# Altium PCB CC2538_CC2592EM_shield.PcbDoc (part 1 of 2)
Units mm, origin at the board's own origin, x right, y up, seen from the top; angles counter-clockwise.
Board outline 41.63 x 56.78 mm, 4 copper layers (TOP, L2, L3, BOTTOM), stack 1.596 mm thick; 77 components, 70 nets, 284 pads, 581 vias.
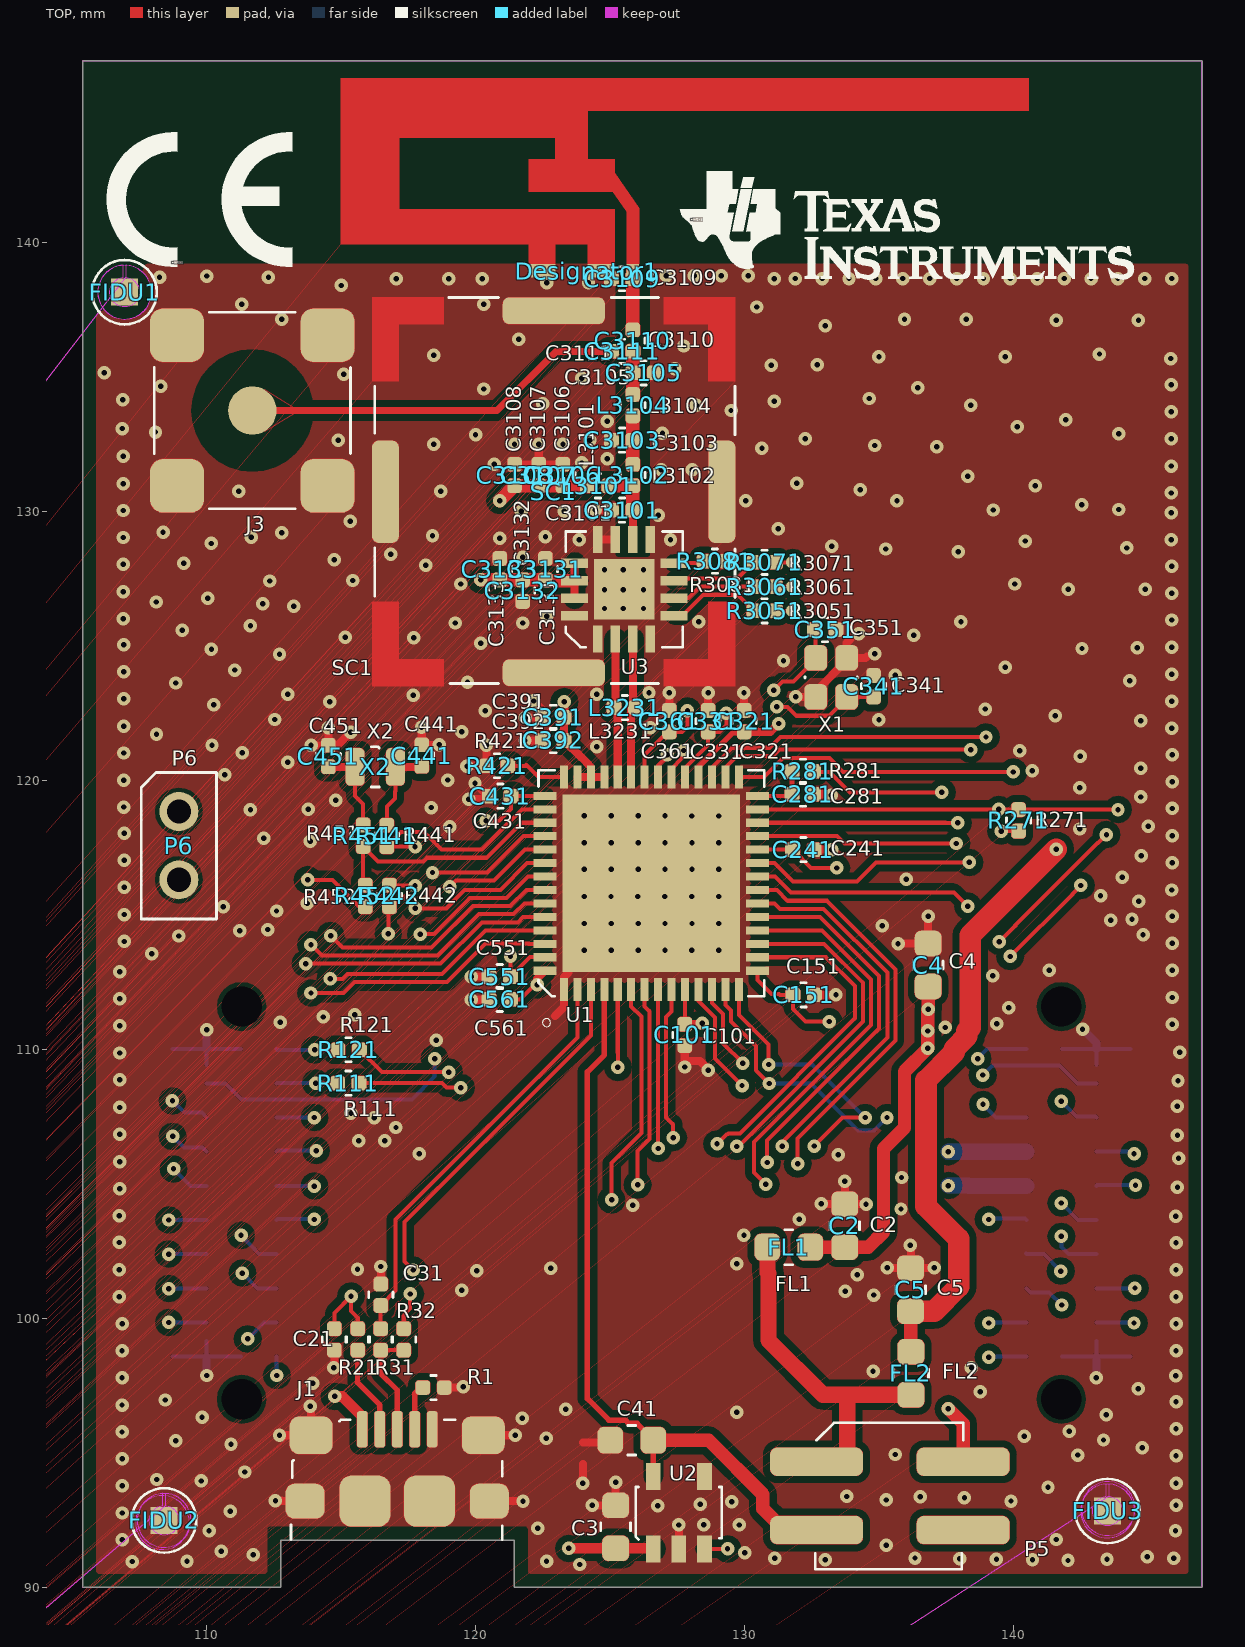
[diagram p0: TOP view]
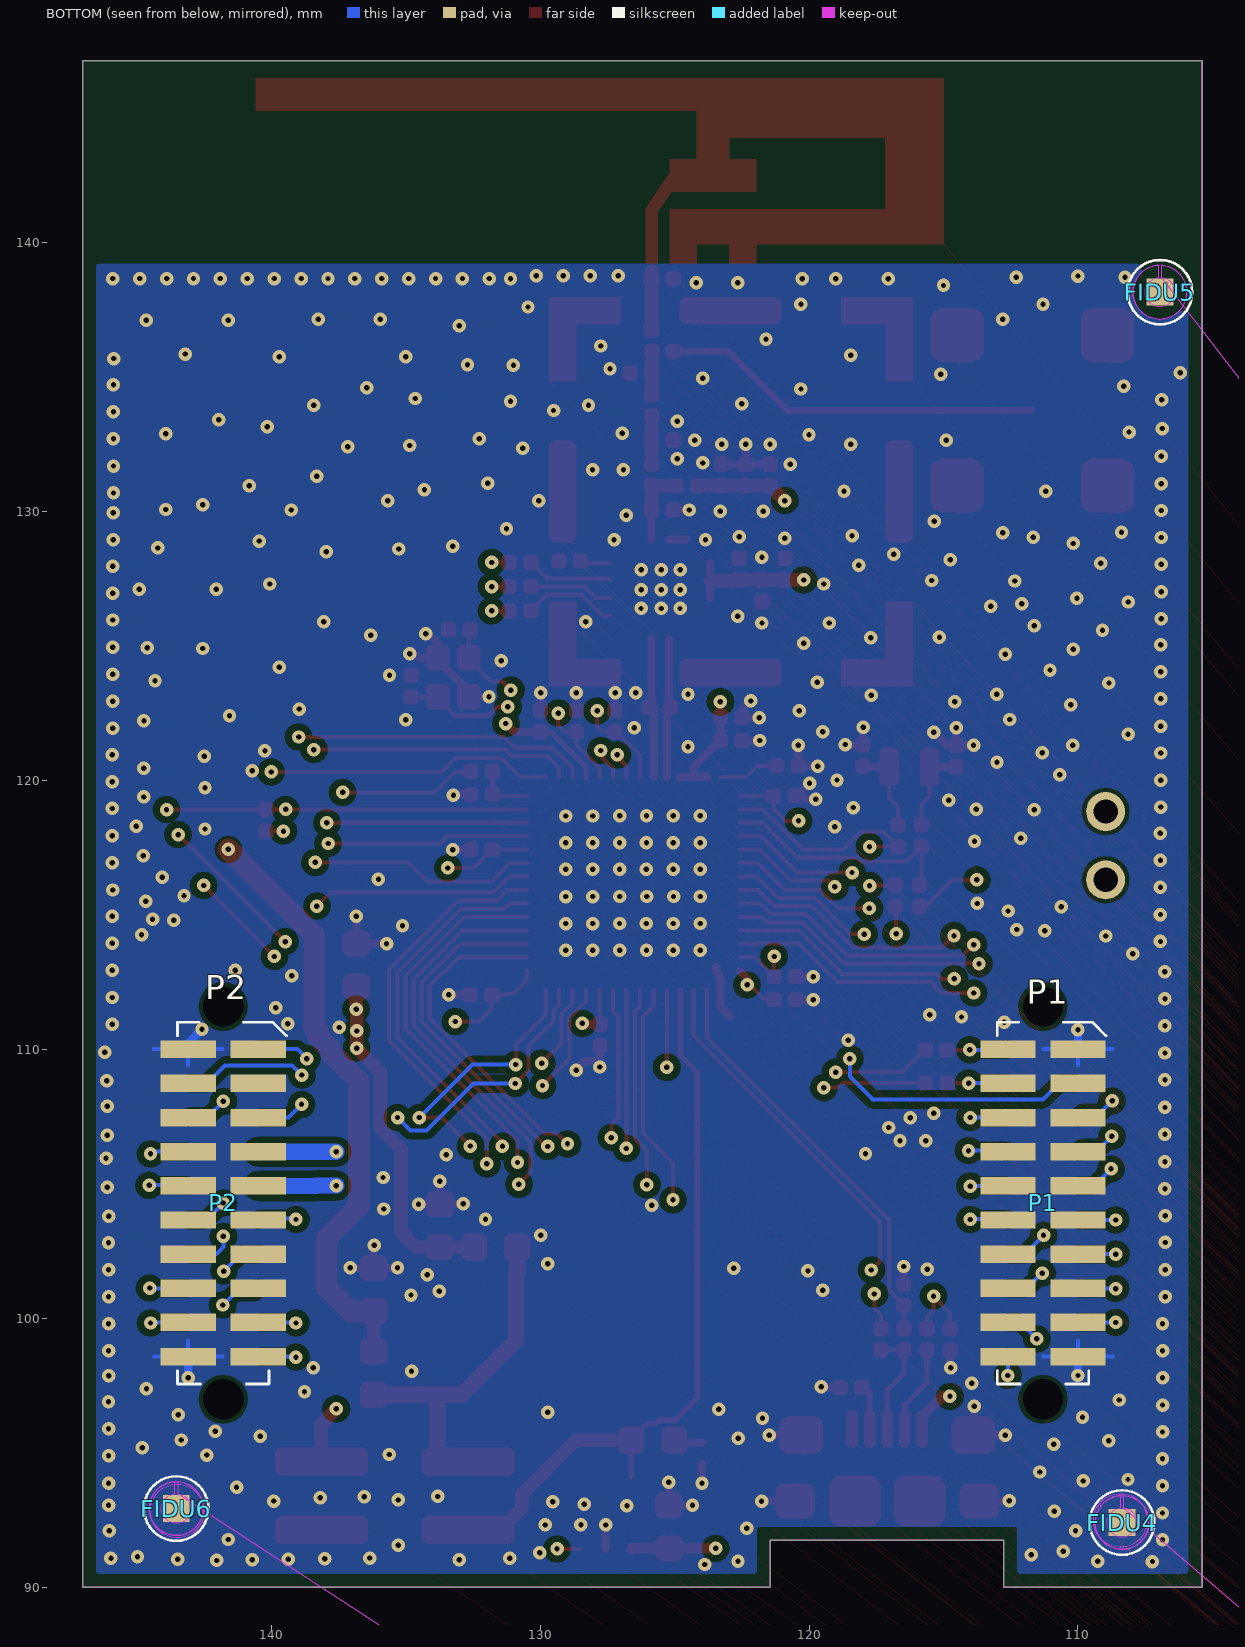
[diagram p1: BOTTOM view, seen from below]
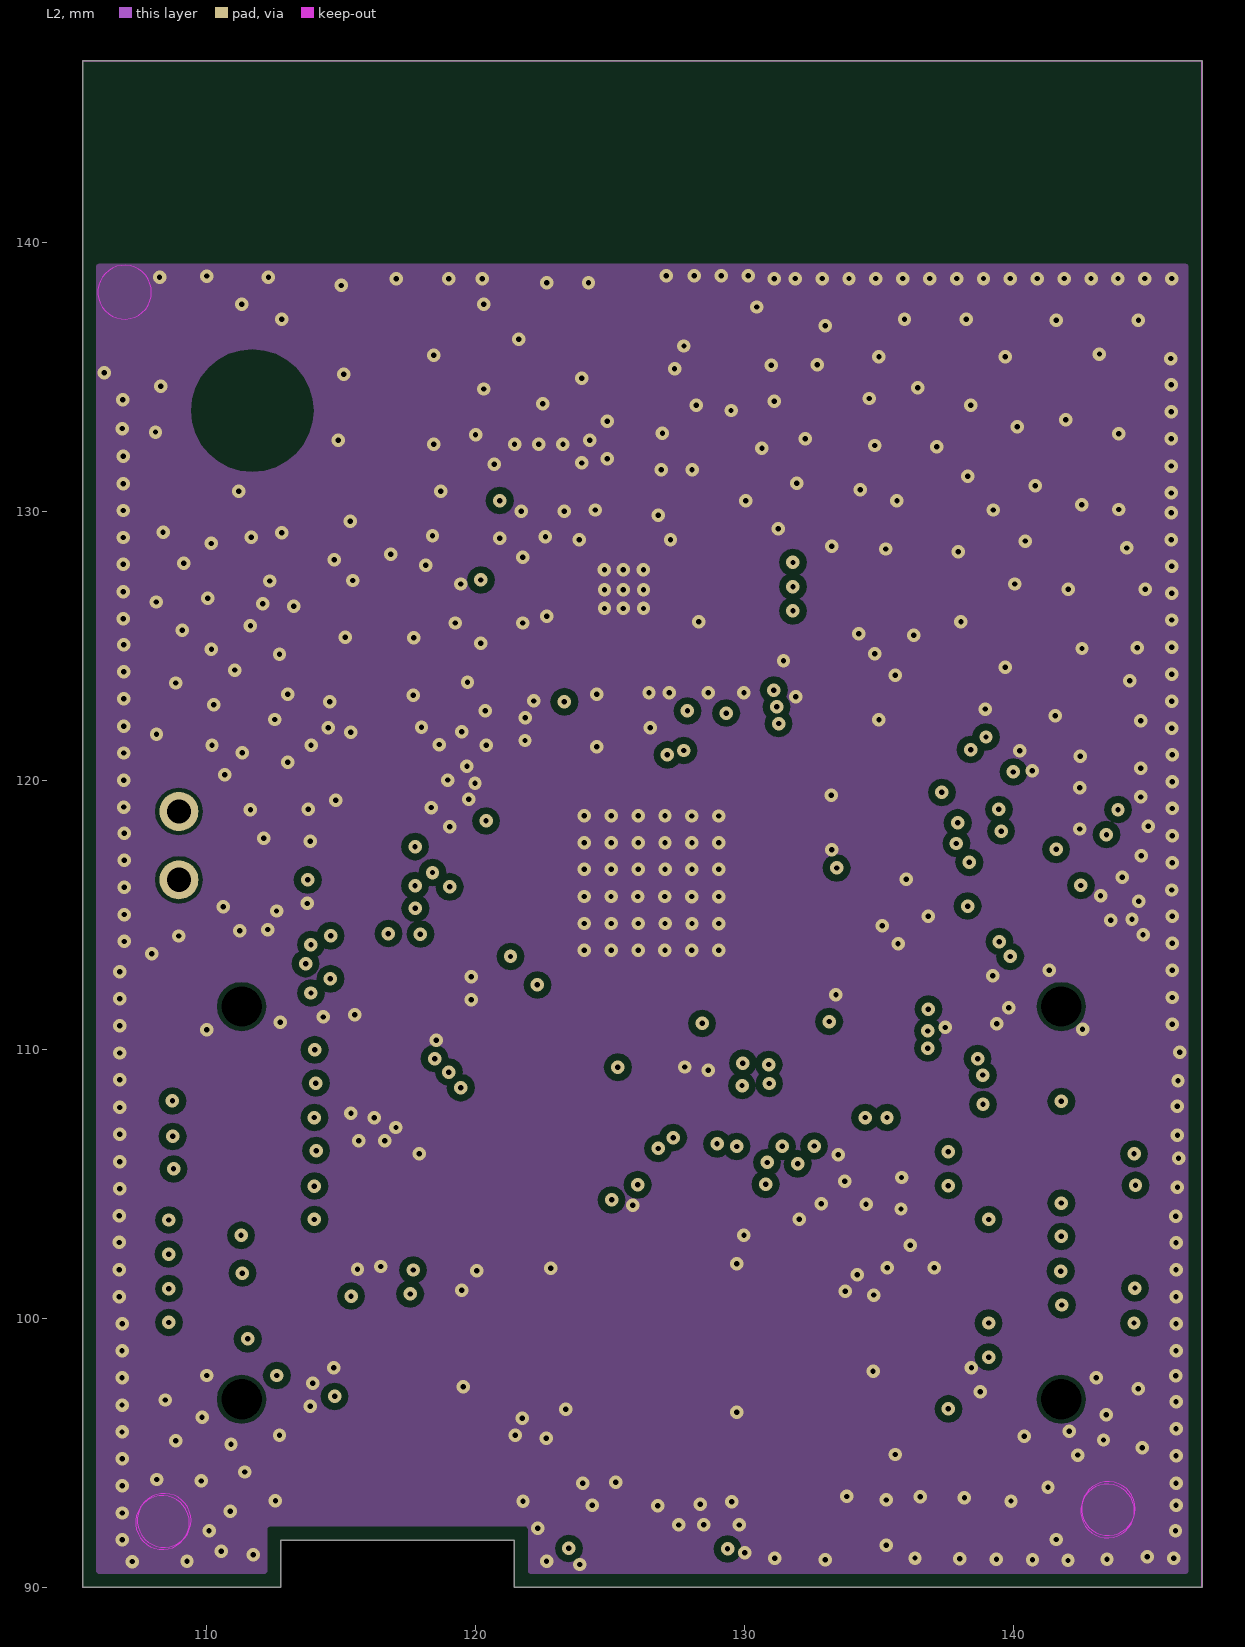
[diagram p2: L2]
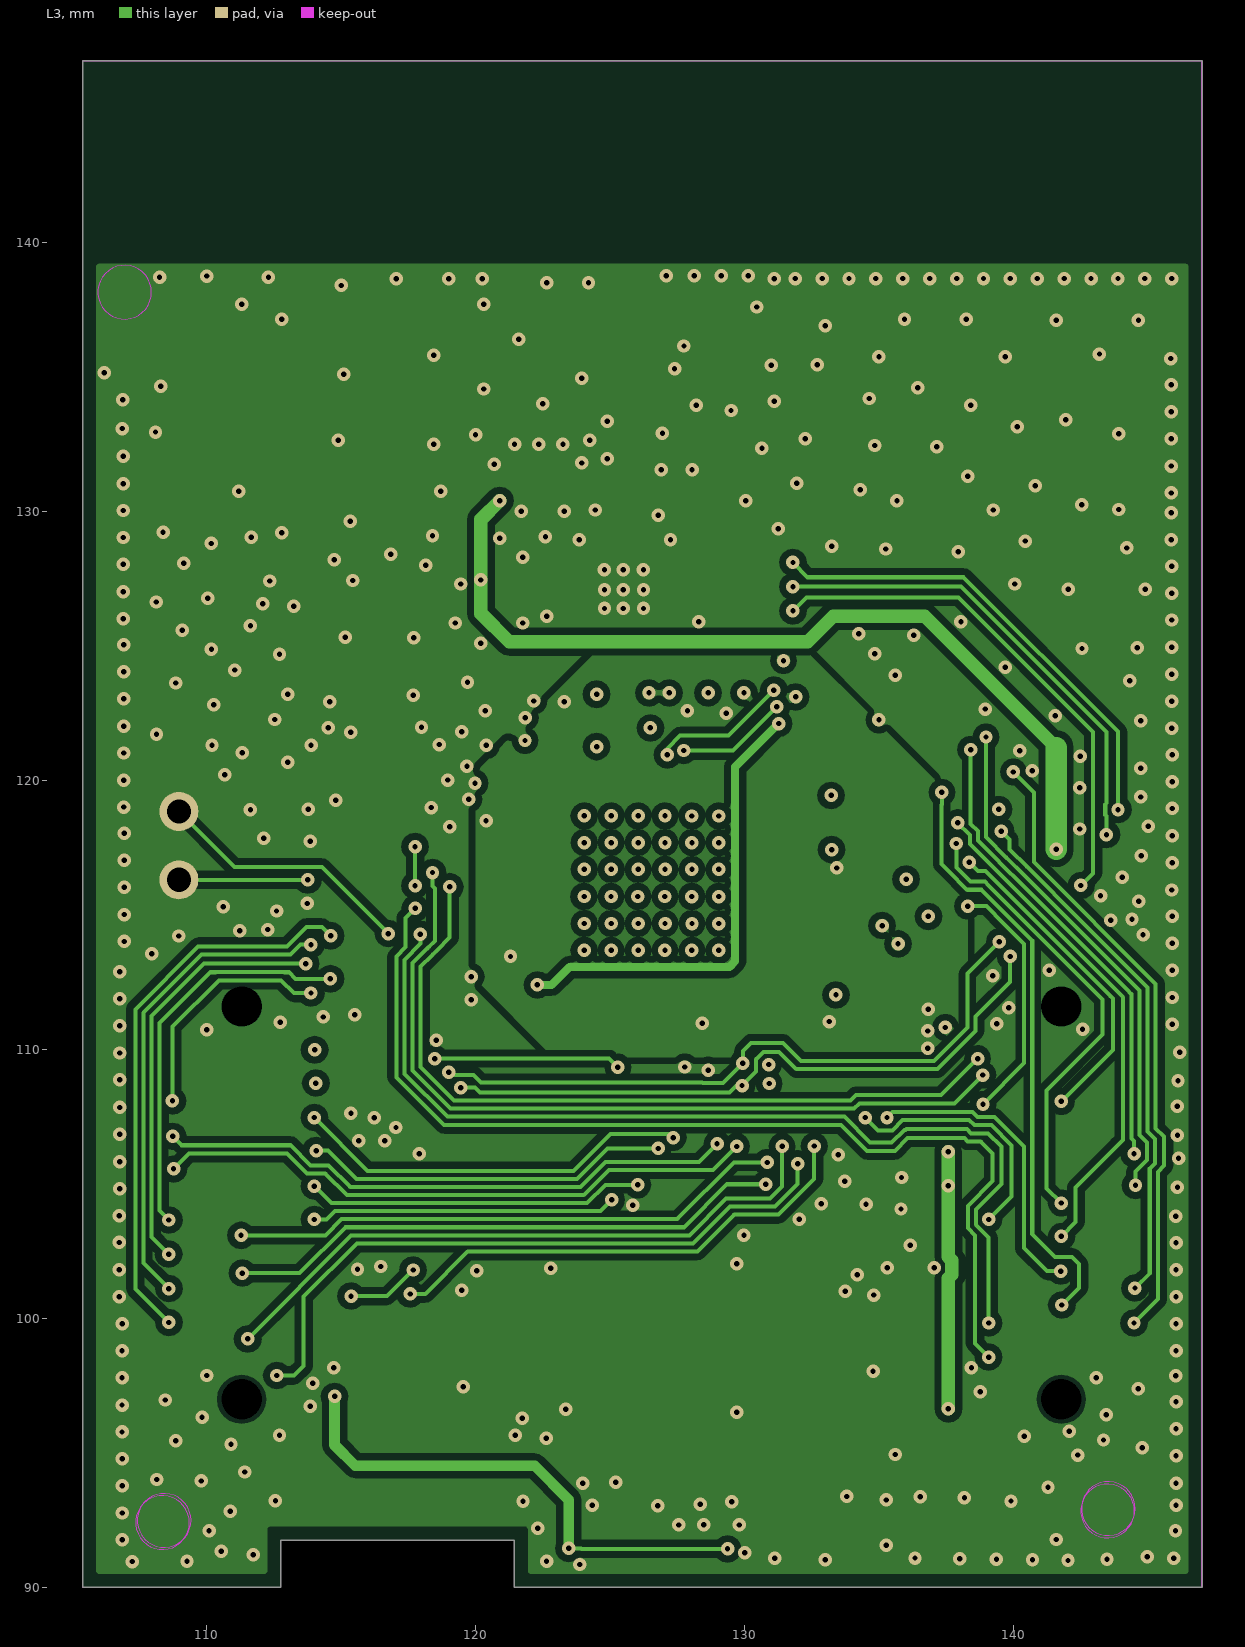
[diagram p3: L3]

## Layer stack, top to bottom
Top Solder: solder mask 0.0102, Solder Resist, Dk 3.5
TOP: signal copper 0.035
Dielectric 1: core 0.175, FR-4, Dk 4.5
L2: signal copper 0.018
Dielectric2: core 1.14, FR-4, Dk 4.5
L3: signal copper 0.018
Dielectric3: core 0.175, FR-4, Dk 4.5
BOTTOM: signal copper 0.035
Bottom Solder: solder mask 0.0102, Solder Resist, Dk 3.5

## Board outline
105.387,90 105.4,89.987 112.75,89.987 112.763,90 112.763,91.737 121.437,91.737 121.437,90 121.45,89.987 147,89.987 147.013,90 147.013,146.75 147,146.763 105.4,146.763 105.387,146.75

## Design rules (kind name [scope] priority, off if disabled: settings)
Clearance [All] p1: gap=0.254
PlaneConnect [All] p1: planeconnectstyle=Direct reliefexpansion=0.508 reliefentries=4 reliefconductorwidth=0.254 reliefairgap=0.254
PolygonConnect [All] p1: connectstyle=Direct reliefconductorwidth=0.254 reliefentries=4 polygonreliefangle="90 Angle" airgapwidth=0.254
RoomDefinition CompsKeepin0 [All vs False] p1: confinementstyle=ConfineIn formatcopy=TRUE lockcomponents=FALSE outline 105.9,152.12 146.5,152.12 146.5,90.5 122.1,90.5 122.1,90.09 112.13,90.09 112.13,90.5 105.9,90.5 105.9,152.12
RoutingVias [All] p1: holewidth=0.711 width=1.27 viastyle="Through Hole" minholewidth=0.711 minwidth=1.27 maxholewidth=0.711 maxwidth=1.27
SolderMaskExpansion [All] p1: expansion=0.102
Width [All] p1: maxlimit=0.254 minlimit=0.254 preferedwidth=0.254 impedancedriven=TRUE minimp=35.860000 maximp=35.860000 favimp=35.860000
29 further rules are at their usual default settings.

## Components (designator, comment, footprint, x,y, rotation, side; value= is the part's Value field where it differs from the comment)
C2 "CAPACITOR_CAPC1608X90N_2.2UF" CAPC1608X90N 133.73,103.44 r90 top
C3 "CAPACITOR_CAPC1608X90N_1UF" CAPC1608X90N 125.21,92.24 r90 top
C4 "CAPACITOR_CAPC1608X90N_DNM_CAPC" CAPC1608X90N 136.83,113.13 r90 top
C5 "CAPACITOR_CAPC1608X90N_2.2UF" CAPC1608X90N 136.18,101.06 r90 top
C21 "CAPACITOR_CAPC1005X60L_47PF_CAP" CAPC1005X60L 114.75,99.21 r270 top
C31 "CAPACITOR_CAPC1005X60L_47PF_CAP" CAPC1005X60L 116.48,100.87 r90 top
C41 "CAPACITOR_CAPC1608X90N_1UF" CAPC1608X90N 125.81,95.46 r180 top
C101 "CAPACITOR_CAPC1005X60L_100NF_CA" CAPC1005X60L 127.78,110.53 r270 top
C151 "CAPACITOR_CAPC1005X60L_100NF_CA" CAPC1005X60L 132.2,112.02 r0 top
C241 "CAPACITOR_CAPC1005X60L_100NF_CA" CAPC1005X60L 132.19,117.42 r0 top
C281 "CAPACITOR_CAPC1005X60L_1NF_CAPC" CAPC1005X60L 132.17,119.48 r0 top
C321 "CAPACITOR_CAPC1005X60L_1UF_CAPC" CAPC1005X60L 129.99,122.2 r90 top
C331 "CAPACITOR_CAPC1005X60L_100NF_CA" CAPC1005X60L 128.65,122.2 r90 top
C341 "CAPACITOR_CAPC1005X60L_12PF_CAP" CAPC1005X60L 134.8,123.5 r90 top
C351 "CAPACITOR_CAPC1005X60L_12PF_CAP" CAPC1005X60L 133,125.6 r0 top
C361 "CAPACITOR_CAPC1005X60L_100NF_CA" CAPC1005X60L 127.21,122.2 r90 top
C391 "CAPACITOR_CAPC1005X60L_100NF_CA" CAPC1005X60L 122.89,122.34 r180 top
C392 "CAPACITOR_CAPC1005X60L_220PF_CA" CAPC1005X60L 122.89,121.48 r180 top
C431 "CAPACITOR_CAPC1005X60L_100NF_CA" CAPC1005X60L 120.92,119.41 r180 top
C441 "CAPACITOR_CAPC1005X60L_22PF_CAP" CAPC1005X60L 118,120.92 r90 top
C451 "CAPACITOR_CAPC1005X60L_22PF_CAP" CAPC1005X60L 114.53,120.9 r90 top
C551 "CAPACITOR_CAPC1005X60L_1UF_CAPC" CAPC1005X60L 120.9,112.7 r180 top
C561 "CAPACITOR_CAPC1005X60L_1UF_CAPC" CAPC1005X60L 120.9,111.85 r180 top
C3101 "CAPACITOR_CAPC1005X60L_3PF_CAPC" CAPC1005X60L 125.45,130.05 r180 top
C3103 "CAPACITOR_CAPC1005X60L_2.2PF_CA" CAPC1005X60L 125.45,132.65 r180 top
C3105 "CAPACITOR_CAPC1005X60L_0.2PF_CA" CAPC1005X60L 126.25,135.15 r0 top
C3106 "CAPACITOR_CAPC1005X60L_6.8PF_CA" CAPC1005X60L 123.25,131.35 r90 top
C3107 "CAPACITOR_CAPC1005X60L_1NF_CAPC" CAPC1005X60L 122.35,131.35 r90 top
C3108 "CAPACITOR_CAPC1005X60L_1UF_CAPC" CAPC1005X60L 121.45,131.35 r90 top
C3109 "CAPACITOR_CAPC1005X60L_DNM_CAPC" CAPC1005X60L 125.45,138.65 r180 top
C3110 "CAPACITOR_HOR_CAPC1005X60L_12PF" CAPC1005X60L 125.85,136.35 r90 top
C3111 "CAPACITOR_CAPC1005X60L_DNM_CAPC" CAPC1005X60L 125.45,135.95 r0 top
C3131 "CAPACITOR_CAPC1005X60L_12PF_CAP" CAPC1005X60L 122.6,127.85 r90 top
C3132 "CAPACITOR_CAPC1005X60L_1NF_CAPC" CAPC1005X60L 121.75,127.05 r270 top
C3133 "CAPACITOR_CAPC1005X60L_DNM_CAPC" CAPC1005X60L 120.9,127.85 r90 top
Designator1 "ANTENNA_DN007_ANTENNA_DN007_DN0" ANTENNA_DN007 127.78,142.955 r0 top
FIDU1 "FIDMARK_FID100X115_FIDU_1MM" FID100X115 106.95,138.15 r0 top
FIDU2 "FIDMARK_FID100X115_FIDU_1MM" FID100X115 108.42,92.48 r0 top
FIDU3 "FIDMARK_FID100X115_FIDU_1MM" FID100X115 143.5,92.83 r0 top
FIDU4 "FIDMARK_FID100X115_FIDU_1MM" FID100X115 108.36,92.4 r0 bottom
FIDU5 "FIDMARK_FID100X115_FIDU_1MM" FID100X115 106.95,138.15 r0 bottom
FIDU6 "FIDMARK_FID100X115_FIDU_1MM" FID100X115 143.53,92.92 r0 bottom
FL1 "FILTER_2PIN_FIL_BLM18HE152SN1DN" FIL_BLM18HE152SN1DN 131.65,102.64 r180 top
FL2 "FILTER_2PIN_FIL_BLM18HE152SN1_1" FIL_BLM18HE152SN1DN 136.19,97.95 r270 top
J1 "CONN_USB_MICRO_5+6_S_TYCO_19815" TYCO_19815681N 117.087,93.245 r270 top
J3 "CONN_COAX_1+4_HUSTSAN_SMA10V21T" HUSTSAN_SMA10V21TGGAN 111.7,133.75 r0 top
L3101 "INDUCTOR_INDC1005X60L_4.7NH_IND" INDC1005X60L 124.55,130.95 r0 top
L3102 "INDUCTOR_HOR_INDC1005X60L_1NH_I" INDC1005X60L 125.85,131.35 r90 top
L3104 "INDUCTOR_INDC1005X60L_1.8NH_IND" INDC1005X60L 125.85,133.95 r90 top
L3231 "INDUCTOR_INDC1005X60L_10NH_INDC" INDC1005X60L 125.55,122.7 r180 top
P1 "CONN_HEADER_2X10_P_S_SAMTEC_SFM" SAMTEC_SFM11002AN 111.27,104.285 r180 bottom
P2 "CONN_HEADER_2X10_P_S_SAMTEC_SFM" SAMTEC_SFM11002AN 141.75,104.285 r180 bottom
P5 "CONN_HEADER_2X2_P_S_GRADCONN_BB" GRADCONN_BB02HP041KB3060B00-4N 135.405,93.39 r270 top
P6 "CONN_HEADER_2_TYCO_826629-2B_82" TYCO_826629-2B 108.97,117.57 r270 top
R1 "RESISTOR_RESC1005X40L_DNM_RESC1" RESC1005X40L 118.44,97.42 r180 top
R21 "RESISTOR_RESC1005X40L_33_RESC10" RESC1005X40L 115.62,99.21 r270 top
R31 "RESISTOR_RESC1005X40L_33_RESC10" RESC1005X40L 116.47,99.21 r270 top
R32 "RESISTOR_RESC1005X40L_1.5K_RESC" RESC1005X40L 117.33,99.21 r90 top
R111 "RESISTOR_RESC1005X40L_DNM_RESC1" RESC1005X40L 115.27,108.74 r180 top
R121 "RESISTOR_RESC1005X40L_DNM_RESC1" RESC1005X40L 115.28,109.98 r180 top
R271 "RESISTOR_RESC1005X40L_DNM_RESC1" RESC1005X40L 140.19,118.51 r90 top
R281 "RESISTOR_RESC1005X40L_2.2K_RESC" RESC1005X40L 132.17,120.33 r180 top
R421 "RESISTOR_RESC1005X40L_56K_RESC1" RESC1005X40L 120.8,120.54 r0 top
R441 "RESISTOR_RESC1005X40L_0_RESC100" RESC1005X40L 116.7,117.93 r90 top
R442 "RESISTOR_RESC1005X40L_DNM_RESC1" RESC1005X40L 116.8,115.7 r90 top
R451 "RESISTOR_RESC1005X40L_0_RESC100" RESC1005X40L 115.82,117.94 r90 top
R452 "RESISTOR_RESC1005X40L_DNM_RESC1" RESC1005X40L 115.9,115.7 r90 top
R3051 "RESISTOR_RESC1005X40L_10K_RESC1" RESC1005X40L 130.75,126.3 r180 top
R3061 "RESISTOR_RESC1005X40L_10K_RESC1" RESC1005X40L 130.75,127.2 r180 top
R3071 "RESISTOR_RESC1005X40L_10K_RESC1" RESC1005X40L 130.75,128.1 r180 top
R3081 "RESISTOR_RESC1005X40L_4.7K_RESC" RESC1005X40L 128.9,128.15 r0 top
SC1 "SHIELD_COVER_BMIS-201_MECH_BMIS" MECH_BMIS201 122.905,130.73 r0 top
U1 "IC_RF_CC2538F512_QFN56_1_QFNFC5" QFNFC50P800X800X100-57AN 126.539,116.17 r0 top
U2 "IC_PM_TLV700233_SOT23-5_SOT95P2" SOT95P280X145-5N 127.56,92.77 r0 top
U3 "IC_RF_CC2592_QFN16_2_QFNFC65P40" QFNFC65P400X400X100-17AN 125.525,127.1 r0 top
X1 "XTAL_4_XTAL_FA128N_32MHZ" XTAL_FA128N 133.226,123.826 r90 top
X2 "XTAL_XTAL_FC12MN_32.768KHZ_XTAL" XTAL_FC12MN 116.27,120.5 r180 top

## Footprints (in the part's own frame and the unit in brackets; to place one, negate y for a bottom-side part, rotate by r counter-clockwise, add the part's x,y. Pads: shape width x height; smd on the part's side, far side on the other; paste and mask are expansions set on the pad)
ANTENNA_DN007 [mm] "ANTENNA_DN007"
  rect 0.46x0.5 smd: 1(-1.93,-4.005)
  rect 1x0.5 smd: 2(-3.11,-4.005) 3(-5.31,-4.005)
  TOP region: -12.79,-3.015 -12.79,3.155 12.79,3.155 12.79,1.945 -3.61,1.945 -3.61,0.145 -2.61,0.145 -2.61,-0.357 -1.7,-1.677 -1.7,-3.755 -2.16,-3.755 -2.16,-1.82 -2.681,-1.065 -5.81,-1.065 -5.81,0.145 -4.81,0.145 -4.81,0.945 -10.61,0.945 -10.61,-1.725 -2.61,-1.725 -2.61,-3.755 -3.61,-3.755 -3.61,-3.015 -4.81,-3.015 -4.81,-3.755 -5.81,-3.755 -5.81,-3.015 -12.79,-3.015 -127.78,-142.955
CAPC1005X60L [mm] "CAPC1005X60L"
  rrect50% 0.55x0.54 smd: 1(-0.4,0) 2(0.4,0)
  silkscreen extent -0.1,-0.45 0.1,0.45
CAPC1608X90N [mm] "CAPC1608X90N"
  rrect50% 0.954x1 smd: 1(-0.8,0) 2(0.8,0)
  silkscreen extent -0.15,-0.55 0.15,0.55
FID100X115 [mm] "FID100X115"
  rrect0% 1x1 smd: 1(0,0)
  TOP keep-out region: 0.05,0.55 0.05,0.55 0.098,0.543 0.144,0.532 0.19,0.518 0.235,0.499 0.277,0.477 0.317,0.451 0.355,0.421 0.391,0.389 0.423,0.353 0.452,0.315 0.478,0.274 0.5,0.231 0.518,0.187 0.532,0.141 0.542,0.094 0.548,0.046 0.55,-0.002 0.548,-0.05 0.541,-0.098 0.53,-0.144 0.516,-0.19 0.497,-0.235 0.475,-0.277 0.449,-0.317 0.419,-0.355 0.387,-0.391 0.351,-0.423 0.313,-0.452 0.272,-0.478 0.229,-0.5 0.185,-0.518 0.139,-0.532 0.092,-0.542 0.044,-0.548 0,-0.55 0,-0.55 -0.048,-0.548 -0.096,-0.541 -0.143,-0.531 -0.188,-0.516 -0.233,-0.498 -0.275,-0.476 -0.316,-0.45 -0.354,-0.42 -0.389,-0.388 -0.422,-0.352 -0.451,-0.314 -0.477,-0.274 -0.499,-0.231 -0.517,-0.187 -0.531,-0.141 -0.542,-0.094 -0.548,-0.046 -0.55,0.002 -0.548,0.05 -0.541,0.098 -0.531,0.145 -0.516,0.19 -0.498,0.235 -0.476,0.277 -0.45,0.318 -0.42,0.356 -0.388,0.391 -0.352,0.424 -0.314,0.453 -0.274,0.479 -0.231,0.501 -0.187,0.519 -0.141,0.533 -0.094,0.544 -0.05,0.55 -0.05,1 -0.05,1.001 -0.137,0.992 -0.223,0.977 -0.307,0.953 -0.389,0.923 -0.468,0.885 -0.543,0.841 -0.614,0.791 -0.681,0.734 -0.742,0.672 -0.798,0.604 -0.847,0.533 -0.89,0.457 -0.927,0.377 -0.956,0.295 -0.978,0.21 -0.992,0.124 -0.999,0.037 -0.999,-0.05 -0.99,-0.137 -0.975,-0.223 -0.951,-0.307 -0.921,-0.389 -0.883,-0.468 -0.839,-0.543 -0.789,-0.614 -0.732,-0.681 -0.67,-0.742 -0.602,-0.798 -0.531,-0.847 -0.455,-0.89 -0.375,-0.927 -0.293,-0.956 -0.208,-0.978 -0.122,-0.992 -0.035,-0.999 0,-1 0,-1 0.087,-0.996 0.174,-0.985 0.259,-0.966 0.342,-0.939 0.423,-0.906 0.5,-0.865 0.574,-0.818 0.643,-0.765 0.708,-0.706 0.766,-0.642 0.82,-0.572 0.866,-0.499 0.907,-0.421 0.94,-0.34 0.966,-0.257 0.985,-0.172 0.996,-0.085 1,0.002 0.996,0.089 0.985,0.176 0.966,0.261 0.939,0.344 0.906,0.425 0.865,0.502 0.818,0.576 0.765,0.645 0.706,0.71 0.642,0.768 0.572,0.822 0.499,0.868 0.421,0.909 0.34,0.942 0.257,0.968 0.172,0.987 0.085,0.998 0.05,1 0.05,0.55 -106.95,-138.15
  Multi-Layer keep-out circle w0.025: c0,0 r1
  silkscreen extent -1.2,-1.2 1.2,1.2
FIL_BLM18HE152SN1DN [mm] "FIL_BLM18HE152SN1DN"
  rrect50% 0.954x1 smd: 1(-0.8,0) 2(0.8,0)
  silkscreen extent -0.15,-0.65 0.15,0.65
GRADCONN_BB02HP041KB3060B00-4N [mm] "GRADCONN_BB02HP041KB3060B00-4N"
  rrect50% 1.05x3.45 smd: 1(-1.27,-2.725) 2(-1.27,2.725) 3(1.27,-2.725) 4(1.27,2.725)
  silkscreen extent -2.72,-2.78 2.73,2.73
HUSTSAN_SMA10V21TGGAN [mm] "HUSTSAN_SMA10V21TGGAN"
  round 1.801 smd: 1(0,0)
  rrect48% 2x2 smd: 2(-2.8,-2.8) 3(2.8,-2.8) 4(2.8,2.8) 5(-2.8,2.8)
  silkscreen extent -3.65,-3.65 3.65,3.65
INDC1005X60L [mm] "INDC1005X60L"
  rrect50% 0.55x0.54 smd: 1(-0.4,0) 2(0.4,0)
  silkscreen extent -0.1,-0.45 0.1,0.45
MECH_BMIS201 [mm] "MECH_BMIS201"
  oct 0.025x0.025 smd: 1(-6.255,-6.73) 3(6.255,-6.73) 5(6.255,6.73) 7(-6.255,6.73)
  rrect50% 3.8x1 smd: 2(0.005,-6.73) 6(0.005,6.73)
  rrect50% 1x3.8 smd: 4(6.255,0) 8(-6.255,0)
  silkscreen extent -6.65,-7.13 6.75,7.22
QFNFC50P800X800X100-57AN [mm] "QFNFC50P800X800X100-57AN"
  rrect0% 0.3x0.851 smd: 1(-3.25,-3.949) 2(-2.75,-3.949) 3(-2.249,-3.949) 4(-1.749,-3.949) 5(-1.251,-3.949) 6(-0.751,-3.949) 7(-0.25,-3.949) 8(0.25,-3.949) 9(0.75,-3.949) 10(1.251,-3.949) 11(1.751,-3.949) 12(2.249,-3.949) 13(2.75,-3.949) 14(3.25,-3.949) 29(3.25,3.95) 30(2.75,3.95) 31(2.249,3.95) 32(1.751,3.95) 33(1.251,3.95) 34(0.75,3.95) 35(0.25,3.95) 36(-0.25,3.95) 37(-0.751,3.95) 38(-1.251,3.95) 39(-1.749,3.95) 40(-2.249,3.95) 41(-2.75,3.95) 42(-3.25,3.95)
  rrect0% 0.851x0.3 smd: 15(3.951,-3.251) 16(3.951,-2.75) 17(3.951,-2.25) 18(3.951,-1.75) 19(3.951,-1.249) 20(3.951,-0.749) 21(3.951,-0.251) 22(3.951,0.249) 23(3.951,0.75) 24(3.951,1.25) 25(3.951,1.751) 26(3.951,2.251) 27(3.951,2.749) 28(3.951,3.249) 43(-3.951,3.249) 44(-3.951,2.749) 45(-3.951,2.251) 46(-3.951,1.751) 47(-3.951,1.25) 48(-3.951,0.75) 49(-3.951,0.249) 50(-3.951,-0.251) 51(-3.951,-0.749) 52(-3.951,-1.249) 53(-3.951,-1.75) 54(-3.951,-2.25) 55(-3.951,-2.75) 56(-3.951,-3.251)
  rect 6.599x6.599 smd: 57(0.001,0)
  silkscreen extent -4.2,-5.33 4.2,4.2
QFNFC65P400X400X100-17AN [mm] "QFNFC65P400X400X100-17AN"
  rrect0% 0.35x1 smd: 1(-0.975,-1.85) 2(-0.325,-1.85) 3(0.325,-1.85) 4(0.975,-1.85) 9(0.975,1.85) 10(0.325,1.85) 11(-0.325,1.85) 12(-0.975,1.85)
  rrect0% 1x0.35 smd: 5(1.85,-0.975) 6(1.85,-0.325) 7(1.85,0.325) 8(1.85,0.975) 13(-1.85,0.975) 14(-1.85,0.325) 15(-1.85,-0.325) 16(-1.85,-0.975)
  rect 2.25x2.25 smd: 17(0,0)
  silkscreen extent -2.17,-2.15 2.18,2.15
RESC1005X40L [mm] "RESC1005X40L"
  rrect50% 0.55x0.54 smd: 1(-0.4,0) 2(0.4,0)
  silkscreen extent -0.1,-0.45 0.1,0.45
SAMTEC_SFM11002AN [mm] "SAMTEC_SFM11002AN"
  rrect0% 2.05x0.65 smd: 1(1.27,5.715) 2(-1.334,5.715) 3(1.27,4.445) 4(-1.334,4.445) 5(1.27,3.175) 6(-1.334,3.175) 7(1.27,1.905) 8(-1.334,1.905) 9(1.27,0.635) 10(-1.334,0.635) 11(1.27,-0.635) 12(-1.334,-0.635) 13(1.27,-1.905) 14(-1.334,-1.905) 15(1.27,-3.175) 16(-1.334,-3.175) 17(1.27,-4.445) 18(-1.334,-4.445) 19(1.27,-5.715) 20(-1.334,-5.715)
  round 0.099 hole 1.501: " "(-0.032,-7.303) " "(-0.032,7.303)
  silkscreen extent -1.73,-6.74 2.32,6.71
SOT95P280X145-5N [mm] "SOT95P280X145-5N"
  rrect0% 0.549x1.001 smd: 1(-0.95,-1.35) 2(0,-1.35) 3(0.95,-1.35) 4(0.95,1.35) 5(-0.95,1.35)
  silkscreen extent -1.6,-1 1.6,0.95
TYCO_826629-2B [mm] "TYCO_826629-2B"
  round 1.45 hole 0.9: 1(-1.27,0) 2(1.27,0)
  silkscreen extent -2.72,-1.4 2.73,1.4
TYCO_19815681N [mm] "TYCO_19815681N"
  rrect50% 1.35x0.4 smd: 1(-2.625,-1.297) 2(-2.625,-0.647) 3(-2.625,0.003) 4(-2.625,0.653) 5(-2.625,1.303)
  rrect50% 1.4x1.6 smd: 6(-2.4,-3.2) 7(-2.4,3.2)
  rrect50% 1.3x1.45 smd: 8(0.05,-3.425) 9(0.05,3.425)
  rrect48% 1.9x1.9 smd: 10(0.05,-1.2) 11(0.05,1.2)
  silkscreen extent -2.98,-3.95 1.48,3.9
XTAL_FA128N [mm] "XTAL_FA128N"
  rrect46% 0.95x0.848 smd: 1(-0.726,-0.574) 2(0.724,-0.574) 3(0.724,0.577) 4(-0.726,0.577)
  silkscreen extent -0.08,-0.97 0.02,0.97
XTAL_FC12MN [mm] "XTAL_FC12MN"
  rrect50% 0.7x1.402 smd: 1(-0.75,0) 2(0.75,0)
  silkscreen extent -0.15,-0.75 0.15,0.75

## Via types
v1: diameter 0.5, hole 0.2, TOP to BOTTOM, 581 vias

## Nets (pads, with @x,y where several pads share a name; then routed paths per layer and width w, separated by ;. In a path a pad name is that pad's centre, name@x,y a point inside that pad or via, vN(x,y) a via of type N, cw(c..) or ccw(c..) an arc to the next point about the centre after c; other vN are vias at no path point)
DVDD_USB: C41.1 P5.3 U1.4 U2.5 | length 27.7
  TOP w0.2: U1.4@124.79,112.221 124.79,109.79 124.16,109.16 124.16,97.01 124.96,96.21 125.57,96.21 125.693,96.088 126.008,96.088 126.61,95.485 C41.1@126.61,95.46 U2.5@126.61,94.12 ; P5.3@132.67,92.11 P5.3@132.68,92.12
  TOP w0.5: C41.1@126.61,95.46 128.67,95.46 130.687,93.443 130.687,92.913 131.48,92.12 P5.3@132.68,92.12
GND: C2.2 C3.2 C4.2 C5.2 C21.2 C31.2 C41.2 C101.2 C151.2 C241.2 C281.2 C321.2 C331.2 C341.2 C351.2 C361.2 C391.2 C392.2 C431.2 C441.2 C451.2 C551.2 C561.2 C3101.2 C3103.2 C3105.2 C3106.2 C3107.2 C3108.2 C3109.2 C3131.2 C3132.2 C3133.2 J1.5 J1.6 J1.7 J1.8 J1.9 J1.10 J1.11 J3.2 J3.3 J3.4 J3.5 P1.1 P1.19 P2.2 P2.20 R1.1 R421.1 R3081.2 SC1.1 SC1.2 SC1.3 SC1.4 SC1.5 SC1.6 SC1.7 SC1.8 U1.1 U1.57 U2.2 U3.1 U3.4 U3.9 U3.11 U3.12 U3.16 U3.17 X1.2 X1.4 | length 61.1
  TOP w0.15: C561.2@120.49,111.84 C561.2@120.5,111.85 ; C551.2@120.5,112.6 C551.2@120.5,112.7 ; C41.2@124.92,95.37 C41.2@125.01,95.46
  TOP w0.3: v1(112.56,93.21) 112.78,93.21 112.795,93.195 J1.8@113.662,93.195 ; v1(112.71,95.64) 112.95,95.64 112.955,95.645 J1.6@113.887,95.645 113.887,96.563 113.85,96.6 v1(113.85,96.722) ; v1(113.883,121.31) 113.99,121.31 114,121.3 C451.2@114.53,121.3 ; v1(114.52,121.952) 114.52,121.82 114.53,121.81 C451.2@114.53,121.3 ; v1(114.73,98.158) 114.73,98.17 114.75,98.19 C21.2@114.75,98.81 ; v1(115.36,121.79) 114.87,121.3 C451.2@114.53,121.3 ; C31.2@116.48,101.27 v1(116.48,101.922) ; v1(117.99,121.972) 117.99,121.73 118,121.72 C441.2@118,121.32 118.56,121.32 118.57,121.33 v1(118.647,121.33) ; R1.1@118.84,97.42 119.4,97.42 119.43,97.45 v1(119.542,97.45) ; v1(119.68,120.52) 119.7,120.54 R421.1@120.4,120.54 v1(120.4,121.3) ; v1(119.75,119.3) 120.32,119.3 120.43,119.41 C431.2@120.46,119.41 ; v1(119.838,111.84) C561.2@120.49,111.84 ; v1(119.838,112.7) C551.2@120.5,112.7 ; v1(119.98,119.89) C431.2@120.46,119.41 ; J1.7@120.287,95.645 v1(121.475,95.645) ; J1.9@120.512,93.195 v1(121.765,93.195) ; C431.2@120.52,119.41 C431.2@120.46,119.41 ; C3108.2@121.45,131.75 C3107.2@122.35,131.75 ; v1(121.838,121.48) C392.2@122.49,121.48 ; v1(121.848,122.33) 122.01,122.33 122.02,122.34 122.5,122.34 122.5,122.62 v1(122.17,122.95) ; v1@122.35,132.3 C3107.2@122.35,131.75 ; 122.96,111.24 123.289,111.569 123.289,112.689 123.45,112.85 U1.57@123.45,113.05 ; C3106.2@123.25,131.75 C3107.2@122.35,131.75 ; v1(123.98,93.868) 123.98,94.06 123.99,94.07 123.99,94.57 ; 123.99,95.37 C41.2@124.92,95.37 ; v1(124.333,93.05) 124.44,93.05 124.45,93.04 C3.2@125.21,93.04 125.21,93.8 125.22,93.81 v1(125.22,93.892) ; v1(124.45,130.05) C3101.2@125.05,130.05 ; U3.12@124.55,128.95 U3.11@125.2,128.95 ; v1(127.2,123.252) 127.2,123.2 127.21,123.19 C361.2@127.21,122.6 ; U2.2@127.56,91.42 v1(127.56,92.31) ; v1(127.78,109.339) v1@127.78,109.562 ; C101.2@127.78,110.13 v1@127.78,109.562 ; v1(128.48,92.32) v1@128.49,92.31 ; v1(128.65,109.22) 128.65,109.262 128.35,109.562 v1@127.78,109.562 ; C331.2@128.65,122.6 v1(128.65,123.252) ; v1(129.98,123.252) 129.98,122.61 C321.2@129.99,122.6 ; v1(131.9,123.1) X1.4@132.649,123.1 132.649,123.299 133.8,124.45 X1.2@133.8,124.55 ; C281.2@132.57,119.48 133.16,119.48 133.2,119.44 v1(133.222,119.44) ; C241.2@132.59,117.42 v1(133.242,117.42) ; C151.2@132.6,112.02 v1(133.401,112.02) ; v1(132.853,104.25) 133.05,104.25 133.06,104.24 C2.2@133.73,104.24 ; v1(133.73,105.092) C2.2@133.73,104.24 ; 133.95,125.25 133.8,125.1 X1.2@133.8,124.55 ; v1(134.52,104.238) 134.518,104.24 C2.2@133.73,104.24 ; 134.55,124.6 134.5,124.55 X1.2@133.8,124.55 ; v1(135.303,101.87) 135.46,101.87 135.47,101.86 C5.2@136.18,101.86 ; v1(135.71,113.92) 135.72,113.93 C4.2@136.83,113.93 136.83,114.93 v1(136.84,114.94) ; v1(136.16,102.712) 136.16,102.64 136.19,102.61 136.19,101.87 C5.2@136.18,101.86 ; v1(137.057,101.88) 136.91,101.88 136.89,101.86 C5.2@136.18,101.86
  BOTTOM w0.15: 108.723,98.57 P1.19@110,98.57 ; 108.723,110 P1.1@110,110 ; 110,99.147 P1.19@110,98.57 ; 110,109.423 P1.1@110,110 ; 111.277,98.57 P1.19@110,98.57 ; 111.277,110 P1.1@110,110 ; 141.807,98.57 P2.20@143.084,98.57 ; 141.807,110 P2.2@143.084,110 ; 143.084,99.147 P2.20@143.084,98.57 ; 143.084,109.423 P2.2@143.084,110 ; 144.361,98.57 P2.20@143.084,98.57 ; 144.361,110 P2.2@143.084,110
  BOTTOM w0.3: v1(110,97.868) P1.19@110,98.57 ; P1.1@110,110 v1(110,110.73) ; v1(142.571,110.749) 143.084,110.236 P2.2@143.084,110 ; v1(143.084,97.784) P2.20@143.084,98.57
  other v1: 123.88,90.84 107.23,90.95 109.27,90.96 122.64,90.96 142.03,90.99 133.01,91.01 140.71,91.01 139.37,91.04 143.48,91.04 131.13,91.07 138.01,91.05 145.957,91.067 136.34,91.08 144.97,91.13 111.74,91.2 130.01,91.28 110.547,91.326 135.27,91.56 106.857,91.756 141.6,91.77 110.09,92.1 146.027,92.097 122.31,92.19 129.81,92.31 106.857,92.756 110.877,92.816 126.77,93.02 146.047,93.037 128.36,93.08 129.53,93.17 139.91,93.2 135.27,93.24 138.18,93.32 133.8,93.37 136.54,93.36 141.287,93.717 106.857,93.772 146.047,93.867 109.807,93.946 108.14,94 111.42,94.28 106.857,94.772 146.047,94.883 135.61,94.93 142.39,94.91 144.797,95.177 110.907,95.316 108.857,95.436 143.35,95.47 122.63,95.54 140.4,95.61 106.855,95.769 142.077,95.797 146.047,95.883 121.73,96.28 109.83,96.32 143.45,96.41 129.711,96.499 123.361,96.611 106.855,96.769 146.048,96.886 108.467,96.956 138.76,97.27 144.637,97.377 113.95,97.58 106.855,97.785 146.032,97.864 134.78,98.03 138.44,98.16 106.855,98.785 146.047,98.787 106.856,99.788 146.047,99.787 106.755,100.799 146.047,100.803 134.8,100.86 133.75,101 119.49,101.04 134.2,101.62 120.04,101.76 106.755,101.799 146.047,101.803 115.61,101.82 122.794,101.86 129.711,102.029 146.048,102.806 106.755,102.815 129.98,103.08 132.03,103.68 146.032,103.784 106.755,103.815 135.82,104.06 125.85,104.2 106.765,104.819 146.1,104.87 135.84,105.23 106.765,105.819 146.14,105.95 133.487,106.077 117.9,106.12 115.66,106.59 116.617,106.597 146.1,106.8 106.765,106.835 117.04,107.09 116.23,107.45 115.367,107.617 106.765,107.835 146.09,107.88 146.12,108.83 106.765,108.859 106.765,109.859 146.182,109.884 118.54,110.34 137.47,110.81 106.765,110.875 145.902,110.923 139.38,110.95 112.74,111 114.33,111.2 115.507,111.277 139.83,111.54 106.765,111.875 145.902,111.923 139.23,112.73 106.766,112.878 141.33,112.93 145.903,112.939 107.957,113.557 128.045,113.677 129.045,113.677 124.043,113.679 125.043,113.679 126.043,113.679 127.043,113.679 145.903,113.939 106.932,114.008 108.97,114.21 144.82,114.25 111.23,114.41 112.28,114.45 135.117,114.597 124.046,114.675 125.046,114.675 126.046,114.675 127.046,114.675 128.048,114.673 129.048,114.673 143.62,114.79 144.41,114.84 145.903,114.942 106.932,115.008 112.6,115.14 110.62,115.3 113.74,115.42 144.66,115.5 124.038,115.679 125.038,115.679 126.038,115.679 127.038,115.679 128.04,115.677 129.04,115.677 143.24,115.7 145.887,115.921 106.932,116.024 136.01,116.32 144.05,116.39 124.046,116.69 125.046,116.69 126.046,116.69 127.046,116.69 128.047,116.688 129.047,116.688 145.903,116.937 106.932,117.024 144.76,117.19 124.045,117.683 125.045,117.683 126.045,117.683 127.045,117.683 128.047,117.681 129.047,117.681 113.847,117.727 112.13,117.84 145.903,117.937 106.933,118.027 142.46,118.19 119.04,118.27 145.01,118.29 124.044,118.675 125.044,118.675 126.044,118.675 127.044,118.675 128.046,118.673 129.046,118.673 111.63,118.9 113.78,118.93 145.903,118.953 106.917,119.005 118.357,118.987 114.8,119.26 144.74,119.38 142.46,119.72 145.903,119.953 106.917,120.005 118.96,120.01 110.68,120.21 140.7,120.36 144.74,120.45 113.01,120.67 142.49,120.89 145.904,120.956 106.915,121.015 111.33,121.03 140.23,121.1 124.5,121.25 110.2,121.31 108.137,121.707 119.49,121.81 126.5,121.95 145.887,121.935 106.915,122.015 144.73,122.22 112.54,122.26 135,122.25 141.55,122.4 120.36,122.59 138.95,122.65 110.27,122.81 114.577,122.917 145.887,122.935 106.915,123.031 117.68,123.16 113.017,123.197 124.5,123.2 126.45,123.25 108.847,123.617 119.7,123.65 144.32,123.7 135.6,123.9 145.886,123.945 106.915,124.031 111.04,124.1 139.7,124.2 131.45,124.45 112.71,124.69 134.85,124.7 110.18,124.87 142.55,124.9 144.61,124.93 145.886,124.945 106.915,125.034 120.2,125.1 117.7,125.3 115.15,125.32 136.3,125.4 134.25,125.45 109.087,125.577 111.63,125.75 119.25,125.85 121.75,125.85 128.3,125.9 138.05,125.9 145.886,125.96 106.899,126.013 122.65,126.1 124.796,126.39 125.496,126.39 126.246,126.39 113.237,126.477 112.09,126.56 108.13,126.63 110.037,126.767 145.886,126.96 106.899,127.013 124.795,127.083 125.495,127.083 126.245,127.083 142.04,127.11 144.9,127.1 119.45,127.3 140.05,127.3 112.35,127.41 115.44,127.43 124.794,127.825 125.494,127.825 126.244,127.825 145.886,127.964 118.15,128 106.899,128.028 109.147,128.077 114.75,128.2 121.75,128.3 116.85,128.4 137.95,128.5 135.25,128.6 144.22,128.64 133.25,128.7 110.177,128.807 140.44,128.897 145.87,128.942 123.85,128.95 127.25,128.95 120.9,129 106.899,129.028 111.657,129.037 122.6,129.05 118.4,129.1 112.8,129.2 108.38,129.23 131.25,129.35 115.34,129.63 126.8,129.85 145.87,129.942 121.7,130 123.3,130 106.9,130.032 139.25,130.05 143.92,130.07 142.54,130.24 135.67,130.39 130.05,130.4 145.863,130.685 111.2,130.75 118.7,130.75 134.3,130.8 140.81,130.95 106.896,131.031 131.95,131.05 138.3,131.3 126.9,131.55 128.05,131.55 145.863,131.685 120.7,131.75 123.95,131.8 124.9,131.95 106.896,132.047 130.65,132.35 137.15,132.4 134.85,132.45 118.45,132.5 121.45,132.5 122.35,132.5 123.25,132.5 114.9,132.65 124.25,132.65 132.26,132.7 145.864,132.701 120,132.85 126.95,132.9 143.92,132.89 108.1,132.95 106.86,133.08 140.14,133.147 124.9,133.35 141.95,133.4 145.864,133.701 129.5,133.75 138.42,133.94 128.2,133.95 122.5,134 131.1,134.1 106.88,134.15 134.64,134.197 120.3,134.55 136.45,134.6 108.3,134.65 145.864,134.704 123.95,134.95 115.1,135.1 106.2,135.15 127.4,135.3 130.99,135.44 132.7,135.45 145.848,135.683 135,135.75 139.7,135.75 118.45,135.8 143.2,135.85 127.75,136.15 121.6,136.4 133,136.9 141.6,137.1 144.65,137.1 112.8,137.15 135.95,137.15 138.25,137.15 130.45,137.6 111.3,137.7 120.3,137.7 115,138.4 122.65,138.5 124.2,138.5 117.05,138.65 119,138.65 120.25,138.65 131.1,138.65 131.887,138.657 132.887,138.657 133.887,138.657 134.887,138.657 135.887,138.657 136.887,138.657 137.887,138.657 138.887,138.657 139.887,138.657 140.887,138.657 141.887,138.657 142.887,138.657 143.887,138.657 144.887,138.657 145.887,138.657 108.25,138.7 112.3,138.7 110,138.75 127.087,138.757 128.137,138.757 129.137,138.757 130.137,138.757
JTAG_TCK: P2.1 U1.47 | length 35.1
  TOP w0.15: v1(119.04,116.04) 119.27,116.27 120.69,116.27 121.84,117.42 U1.47@122.588,117.42
  L3 w0.15: v1(119.04,116.04) 119.04,114.154 118.56,113.674 118.56,113.672 118.427,113.541 118.373,113.487 117.96,113.075 117.96,109.332 119.202,108.09 133.946,108.09 134.145,108.29 137.31,108.29 v1(138.67,109.65)
  BOTTOM w0.15: v1(138.67,109.65) 139.02,110 P2.1@140.48,110
JTAG_TMS: P2.4 U1.46 | length 39.4
  TOP w0.15: v1(118.4,116.57) 120.43,116.57 121.781,117.921 U1.46@122.588,117.921
  L3 w0.15: v1(118.4,116.57) 118.4,116.063 118.49,115.973 118.49,114.03 118.26,113.801 118.26,113.799 118.215,113.755 117.66,113.2 117.66,109.207 119.077,107.79 134.071,107.79 134.27,107.99 137.81,107.99 v1(138.86,109.04)
  BOTTOM w0.15: v1(138.86,109.04) 139.218,109.398 141.715,109.398 142.384,108.73 P2.4@143.084,108.73
N05346: R421.2 U1.42 | length 2.3
  TOP w0.15: R421.2@121.2,120.54 121.88,120.54 121.9,120.56 122.34,120.12 U1.42@123.289,120.12
N19179: J1.3 R31.2 R32.1 | length 4.1
  TOP w0.15: R31.2@116.47,98.711 R31.2@116.47,98.81 R32.1@117.33,98.81
  TOP w0.2: R31.2@116.47,98.711 116.47,97.94 117.09,97.32 J1.3@117.09,95.87
N23099: C341.1 U1.34 X1.1 | length 9.4
  TOP w0.15: v1(127.739,121.108) 127.685,121.054 127.685,120.821 127.29,120.426 U1.34@127.29,120.121 ; v1(131.196,122.733) 131.595,122.733 131.928,122.4 133.151,122.4 133.8,123.049 X1.1@133.8,123.1 C341.1@134.8,123.1 ; U1.34@127.289,120.12 U1.34@127.29,120.121
  L3 w0.15: v1(127.739,121.108) 129.568,121.108 130.873,122.413 130.876,122.413 v1(131.196,122.733)
N24069: J1.4 R1.2 | length 1.7
  TOP w0.15: J1.4@117.74,95.87 J1.4@117.74,96.25 ; R1.2@117.941,97.42 R1.2@118.04,97.42
  TOP w0.2: J1.4@117.74,96.25 117.74,97.219 R1.2@117.941,97.42
N28244: J1.2 R21.2 | length 3.3
  TOP w0.15: R21.2@115.62,98.711 R21.2@115.62,98.81
  TOP w0.2: R21.2@115.62,98.711 115.62,98.159 115.612,98.151 115.612,97.6 116.44,96.772 J1.2@116.44,95.87
N31525: C351.1 U1.35 X1.3 | length 9.2
  TOP w0.15: U1.35@126.789,120.12 126.789,120.549 127.132,120.892 v1(127.132,120.949) ; v1(131.091,123.352) 131.411,123.672 131.822,123.672 132.649,124.499 X1.3@132.649,124.55 132.649,125.551 C351.1@132.6,125.6
  L3 w0.15: v1(127.132,120.949) 127.132,121.182 127.61,121.66 129.399,121.66 v1(131.091,123.352)
N50825: C3.1 J1.1 U2.1 U2.3 | length 24.9
  TOP w0.15: U2.3@128.51,91.42 v1(129.37,91.42)
  TOP w0.4: v1(114.76,97.09) 115.045,97.09 115.79,96.345 J1.1@115.79,95.87 ; v1(123.47,91.44) C3.1@125.21,91.44 126.59,91.44 U2.1@126.61,91.42
  L3 w0.15: v1(123.47,91.44) 123.922,91.44 123.942,91.42 v1(129.37,91.42)
  L3 w0.4: v1(114.76,97.09) 114.76,95.28 115.53,94.51 122.2,94.51 123.47,93.24 v1(123.47,91.44)
N61958: P2.16 R271.1 | length 21.8
  TOP w0.15: v1(139.543,118.11) R271.1@140.19,118.11
  L3 w0.15: v1(139.543,118.11) 139.863,117.79 139.863,117.428 140.515,116.776 142.5,114.792 144.99,112.302 144.99,106.935 145.261,106.664 145.261,105.756 145.07,105.565 145.07,101.67 v1(144.52,101.12)
  BOTTOM w0.15: P2.16@143.084,101.11 144.51,101.11 v1(144.52,101.12)
N118182: FL1.2 FL2.2 P5.1 | length 13.1
  TOP w0.5: P5.1@132.68,94.66 133.54,94.66 P5.1@133.82,94.94
  TOP w0.6: FL1.2@130.85,102.64 130.85,101.712 130.89,101.672 130.89,99.18 132.92,97.15 133.82,97.15 ; P5.1@133.82,94.94 133.82,97.15 ; FL2.2@136.19,97.15 133.82,97.15
N130966: R3081.1 U3.8 | length 1.2
  TOP w0.15: U3.8@127.375,128.075 128.425,128.075 R3081.1@128.5,128.15
N292030: P1.2 R121.2 | length 2.3
  TOP w0.15: v1(114.02,109.98) R121.2@114.88,109.98
  BOTTOM w0.15: P1.2@112.604,110 112.624,109.98 v1(114.02,109.98)
N292096: P1.4 R111.2 | length 2.3
  TOP w0.15: v1(114.06,108.74) R111.2@114.87,108.74
  BOTTOM w0.15: P1.4@112.604,108.73 112.614,108.74 v1(114.06,108.74)
N302598: C3109.1 C3110.2 | length 2.2
  TOP w0.5: C3110.2@125.85,136.75 C3109.1@125.85,138.65 125.85,138.95
N313805: L3231.1 U1.37 U3.3 | length 5.4
  TOP w0.15: L3231.1@125.788,122.75 125.838,122.7 L3231.1@125.95,122.7
  TOP w0.3: U1.37@125.788,120.12 L3231.1@125.788,122.75 ; U3.3@125.85,125.25 125.85,122.8 L3231.1@125.95,122.7
N313817: L3231.2 U1.38 U3.2 | length 5.3
  TOP w0.15: L3231.2@125.15,122.7 L3231.2@125.288,122.7
  TOP w0.3: L3231.2@125.15,122.7 125.2,122.75 U3.2@125.2,125.25 ; U1.38@125.288,120.12 L3231.2@125.288,122.7
N314459: R3071.2 U3.7 | length 3.3
  TOP w0.15: U3.7@127.375,127.425 127.45,127.5 129.745,127.5 130.345,128.1 R3071.2@130.35,128.1
N314634: R3061.2 U3.6 | length 3.2
  TOP w0.15: U3.6@127.375,126.775 127.925,126.775 128.35,127.2 R3061.2@130.35,127.2
N315094: R3051.2 U3.5 | length 3.5
  TOP w0.15: U3.5@127.375,126.125 127.7,126.125 128.475,126.9 129.745,126.9 130.345,126.3 R3051.2@130.35,126.3
N333392: C3101.1 L3101.2 L3102.1 U3.10 | length 2.9
  TOP w0.3: U3.10@125.85,128.95 C3101.1@125.85,130.05
  TOP w0.5: L3101.2@124.95,130.95 L3102.1@125.85,130.95 C3101.1@125.85,130.05
N333448: C3105.1 C3110.1 C3111.2 L3104.2 | length 1.6
  TOP w0.5: L3104.2@125.85,134.35 C3105.1@125.85,135.15 C3110.1@125.85,135.95
N333456: C3103.1 L3102.2 L3104.1 | length 1.8
  TOP w0.5: L3102.2@125.85,131.75 C3103.1@125.85,132.65 L3104.1@125.85,133.55
N355972: C3111.1 J3.1 | length 14.3
  TOP w0.26: J3.1@111.7,133.75 120.8,133.75 123,135.95 C3111.1@125.05,135.95
N359155: C441.1 R441.2 X2.1 | length 3.3
  TOP w0.15: R441.2@116.7,118.33 116.7,119.02 117,119.32 117,119.577 117.02,119.597 X2.1@117.02,120.5
  TOP w0.3: X2.1@117.02,120.5 117.98,120.5 C441.1@118,120.52
N359159: C451.1 R451.2 X2.2 | length 3.3
  TOP w0.15: X2.2@115.52,120.5 115.52,119.42 115.82,119.12 R451.2@115.82,118.34
  TOP w0.3: C451.1@114.53,120.5 X2.2@115.52,120.5
N359209: R451.1 R452.2 U1.45 | length 9.2
  TOP w0.15: R451.1@115.82,117.54 R451.1@115.82,117.535 ; R452.2@115.9,116.1 115.85,116.1 115.81,116.06 115.81,117.003 115.82,117.013 R451.1@115.82,117.535 ; U1.45@122.588,118.421 121.711,118.421 120.41,117.12 118.201,117.12 118.061,116.98 116.375,116.98 R451.1@115.82,117.535
N359245: R441.1 R442.2 U1.44 | length 10.5
  TOP w0.15: R442.2@116.8,116.1 116.78,116.08 v1(117.75,116.08) ; v1(117.75,117.53) R441.1@116.7,117.53 116.7,117.535 117.235,118.07 118.08,118.07 118.73,117.42 120.233,117.42 121.732,118.919 U1.44@122.588,118.919
  L3 w0.15: v1(117.75,116.08) v1(117.75,117.53)
N359999: C281.1 R281.2 U1.28 | length 3.1
  TOP w0.15: U1.28@130.49,119.419 131.599,119.419 131.75,119.57 R281.2@131.75,120.31 ; C281.1@131.77,119.48 131.791,119.501 R281.2@131.791,120.31 ; R281.2@131.77,120.33 R281.2@131.75,120.31 ; R281.2@131.89,120.31 R281.2@131.791,120.31 ; R281.2@131.75,120.31 R281.2@131.791,120.31
N362623: C321.1 C561.1 U1.32 U1.56 | length 23.1
  TOP w0.15: C561.1@121.3,111.85 121.655,111.85 122.187,112.382 v1@122.29,112.382
  TOP w0.2: U1.32@128.29,120.12 128.291,120.121 128.291,120.491 129.56,121.76 129.95,121.76 C321.1@129.99,121.8
  TOP w0.3: v1(122.3,112.392) 122.29,112.382 122.29,112.621 U1.56@122.588,112.919 ; C321.1@129.99,121.8 130.96,121.8 v1(131.27,122.11)
  L3 w0.3: v1(122.3,112.392) 122.828,112.392 123.496,113.06 129.44,113.06 129.652,113.272 129.652,120.492 v1(131.27,122.11)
